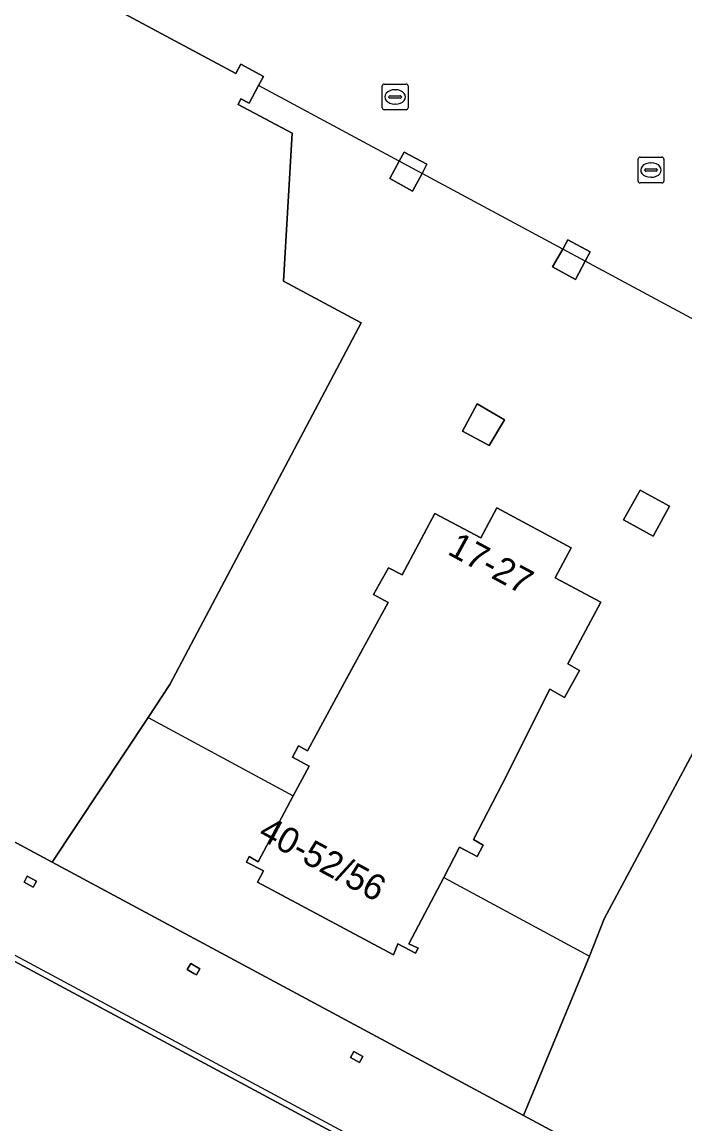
# Model space of a CAD drawing. Extents: x 159489 to 160304, y 383825 to 384531.
# Drawn here: x 159831.19 to 159856.94, y 384203.65 to 384246.47 of the extents above; entities that cross this region are included whole.
import ezdxf

# ---------------------------------------------------------------- set-up
doc = ezdxf.new("R2010")
doc.units = 0
for name, color, linetype in [('IMGEO_Kolk', 7, 'Continuous'), ('IMGEO_Lijnafwatering', 7, 'Continuous'), ('IMGEO_Pand', 7, 'Continuous'), ('IMGEO_Pand_nummerreeks', 7, 'Continuous'), ('IMGEO_Pand_overbouw', 7, 'Continuous'), ('IMGEO_Rioolput', 7, 'Continuous'), ('IMGEO_Voetpad_open', 7, 'Continuous')]:
    doc.layers.add(name, color=color, linetype=linetype)

msp = doc.modelspace()

# ---------------------------------------------------------------- linework, layer by layer
at = {"layer": 'IMGEO_Kolk'}
for p, q in [((159845.183, 384243.138), (159845.183, 384243.99)), ((159845.258, 384244.064), (159846.11, 384244.064)), ((159846.184, 384243.99), (159846.184, 384243.138)), ((159845.442, 384243.558), (159845.442, 384243.57)), ((159845.485, 384243.607), (159845.883, 384243.607)), ((159845.671, 384243.844), (159845.696, 384243.844)), ((159845.926, 384243.57), (159845.926, 384243.558)), ((159845.88, 384243.521), (159845.482, 384243.521)), ((159845.694, 384243.284), (159845.669, 384243.284)), ((159846.11, 384243.064), (159845.258, 384243.064))]:
    msp.add_line(p, q, dxfattribs=at)
for points in [[(159845.183, 384243.138), (159845.183, 384243.99)], [(159845.258, 384244.064), (159846.11, 384244.064)], [(159846.184, 384243.99), (159846.184, 384243.138)], [(159846.11, 384243.064), (159845.258, 384243.064)]]:
    msp.add_lwpolyline(points, dxfattribs=at)
for centre, radius, start, end in [((159845.26, 384243.988), 0.0765, 91.552, 178.448), ((159845.26, 384243.988), 0.0765, 91.552, 178.448), ((159846.108, 384243.988), 0.0765, 1.552, 88.448), ((159846.108, 384243.988), 0.0765, 1.552, 88.448), ((159845.482, 384243.567), 0.0403, 85.8775, 175.7526), ((159845.887, 384243.569), 0.0386, 1.7309, 96.639), ((159845.26, 384243.14), 0.0765, 181.552, 268.448), ((159845.26, 384243.14), 0.0765, 181.552, 268.448), ((159845.479, 384243.557), 0.0366, 178.938, 274.7102), ((159845.883, 384243.564), 0.043, 264.8664, 352.4533), ((159846.108, 384243.14), 0.0765, 271.552, 358.448), ((159846.108, 384243.14), 0.0765, 271.552, 358.448)]:
    msp.add_arc(centre, radius, start, end, dxfattribs=at)
for centre, major_axis, ratio, start_param, end_param in [((159845.67, 384243.564), (-0.387, 0.002), 0.722429, 4.712389, 7.853982), ((159845.695, 384243.564), (-0.39, 0.002), 0.717154, 1.570796, 4.712389)]:
    msp.add_ellipse(centre, major_axis=major_axis, ratio=ratio, start_param=start_param, end_param=end_param, dxfattribs=at)
at = {"layer": 'IMGEO_Lijnafwatering'}
for points in [[(159839.597, 384205.535), (159822.818, 384214.548)], [(159856.376, 384196.522), (159839.597, 384205.535)]]:
    msp.add_lwpolyline(points, dxfattribs=at)
at = {"layer": 'IMGEO_Pand'}
for points in [[(159806.759, 384227.581), (159832.355, 384213.828), (159836.092, 384219.448), (159836.928, 384220.726), (159844.358, 384234.78), (159841.346, 384236.404), (159841.688, 384242.153), (159839.589, 384243.272), (159839.694, 384243.496), (159840.01, 384243.32), (159840.376, 384244.002), (159840.57, 384244.359), (159839.69, 384244.84), (159839.497, 384244.475), (159834.054, 384247.399), (159834.25, 384247.76), (159833.369, 384248.239), (159833.176, 384247.87), (159827.698, 384250.814)], [(159861.301, 384225.632), (159853.801, 384211.617), (159853.229, 384210.167), (159850.676, 384203.98), (159876.265, 384190.214)]]:
    msp.add_lwpolyline(points, dxfattribs=at)
for points in [[(159846.92, 384240.95), (159846.04, 384241.419), (159845.846, 384241.062), (159845.477, 384240.399), (159846.363, 384239.905), (159846.729, 384240.587)], [(159853.26, 384237.539), (159852.39, 384238.01), (159852.199, 384237.648), (159851.793, 384236.955), (159852.69, 384236.473), (159853.07, 384237.18)], [(159849.929, 384231.009), (159848.871, 384231.633), (159848.299, 384230.579), (159849.342, 384230.013)], [(159854.562, 384227.129), (159855.707, 384226.495), (159856.347, 384227.652), (159855.202, 384228.286)], [(159852.846, 384221.265), (159852.392, 384221.529), (159853.673, 384223.928), (159851.9, 384224.877), (159852.52, 384226.034), (159849.631, 384227.59), (159849.008, 384226.426), (159847.232, 384227.377), (159845.952, 384224.987), (159845.425, 384225.265), (159844.841, 384224.225), (159845.41, 384223.915), (159843.988, 384221.304), (159842.274, 384218.155), (159841.928, 384218.344), (159841.698, 384217.902), (159842.342, 384217.559), (159841.725, 384216.397), (159840.363, 384213.832), (159840.01, 384214.04), (159839.913, 384213.826), (159840.567, 384213.482), (159840.331, 384213.041), (159845.618, 384210.218), (159845.788, 384210.654), (159846.476, 384210.283), (159846.574, 384210.481), (159846.211, 384210.648), (159847.571, 384213.231), (159848.188, 384214.403), (159848.871, 384214.044), (159849.102, 384214.486), (159848.722, 384214.704), (159849.86, 384216.884), (159851.696, 384220.543), (159852.263, 384220.225)], [(159831.752, 384213.085), (159831.394, 384213.279), (159831.266, 384213.043), (159831.624, 384212.849)], [(159838.102, 384209.679), (159837.751, 384209.884), (159837.61, 384209.644), (159837.867, 384209.494), (159837.964, 384209.442)], [(159844.433, 384206.265), (159844.085, 384206.457), (159843.956, 384206.224), (159844.305, 384206.032)]]:
    msp.add_lwpolyline(points, close=True, dxfattribs=at)
at = {"layer": 'IMGEO_Pand_overbouw'}
msp.add_lwpolyline([(159858.56, 384234.23), (159853.07, 384237.18), (159852.199, 384237.648), (159846.729, 384240.587), (159845.846, 384241.062), (159840.376, 384244.002), (159840.01, 384243.32), (159839.694, 384243.496), (159839.589, 384243.272), (159841.688, 384242.153), (159841.346, 384236.404), (159844.358, 384234.78), (159836.928, 384220.726), (159836.092, 384219.448), (159841.725, 384216.397), (159842.342, 384217.559), (159841.698, 384217.902), (159841.928, 384218.344), (159842.274, 384218.155), (159845.41, 384223.915), (159844.841, 384224.225), (159845.425, 384225.265), (159845.952, 384224.987), (159847.232, 384227.377), (159849.008, 384226.426), (159849.631, 384227.59), (159852.52, 384226.034), (159851.9, 384224.877), (159853.673, 384223.928), (159852.392, 384221.529), (159852.846, 384221.265), (159852.263, 384220.225), (159851.696, 384220.543), (159849.86, 384216.884), (159848.722, 384214.704), (159849.102, 384214.486), (159848.871, 384214.044), (159848.188, 384214.403), (159847.571, 384213.231), (159853.229, 384210.167), (159853.801, 384211.617), (159861.301, 384225.632)], dxfattribs=at)
at = {"layer": 'IMGEO_Rioolput'}
for p, q in [((159855.123, 384240.296), (159855.123, 384241.148)), ((159855.198, 384241.222), (159856.05, 384241.222)), ((159855.611, 384241.002), (159855.636, 384241.002)), ((159856.124, 384241.148), (159856.124, 384240.296)), ((159855.382, 384240.716), (159855.382, 384240.728)), ((159855.82, 384240.679), (159855.422, 384240.679)), ((159855.425, 384240.765), (159855.823, 384240.765)), ((159855.866, 384240.728), (159855.866, 384240.716)), ((159856.05, 384240.222), (159855.198, 384240.222)), ((159855.634, 384240.442), (159855.609, 384240.442))]:
    msp.add_line(p, q, dxfattribs=at)
for points in [[(159855.123, 384240.296), (159855.123, 384241.148)], [(159855.198, 384241.222), (159856.05, 384241.222)], [(159856.124, 384241.148), (159856.124, 384240.296)], [(159856.05, 384240.222), (159855.198, 384240.222)]]:
    msp.add_lwpolyline(points, dxfattribs=at)
for centre, radius, start, end in [((159855.2, 384241.146), 0.0765, 91.552, 178.448), ((159855.2, 384241.146), 0.0765, 91.552, 178.448), ((159856.048, 384241.146), 0.0765, 1.552, 88.448), ((159856.048, 384241.146), 0.0765, 1.552, 88.448), ((159855.422, 384240.725), 0.0403, 85.8775, 175.7526), ((159855.419, 384240.715), 0.0366, 178.938, 274.7102), ((159855.823, 384240.722), 0.043, 264.8664, 352.4533), ((159855.827, 384240.727), 0.0386, 1.7309, 96.639), ((159855.2, 384240.298), 0.0765, 181.552, 268.448), ((159855.2, 384240.298), 0.0765, 181.552, 268.448), ((159856.048, 384240.298), 0.0765, 271.552, 358.448), ((159856.048, 384240.298), 0.0765, 271.552, 358.448)]:
    msp.add_arc(centre, radius, start, end, dxfattribs=at)
for centre, major_axis, ratio, start_param, end_param in [((159855.61, 384240.722), (-0.387, 0.002), 0.722429, 4.712389, 7.853982), ((159855.635, 384240.722), (-0.39, 0.002), 0.717154, 1.570796, 4.712389)]:
    msp.add_ellipse(centre, major_axis=major_axis, ratio=ratio, start_param=start_param, end_param=end_param, dxfattribs=at)
at = {"layer": 'IMGEO_Voetpad_open'}
for points in [[(159834.054, 384247.399), (159839.497, 384244.475), (159839.69, 384244.84), (159840.57, 384244.359), (159840.376, 384244.002), (159840.01, 384243.32), (159839.694, 384243.496), (159839.589, 384243.272), (159841.688, 384242.153), (159841.346, 384236.404), (159844.358, 384234.78), (159836.928, 384220.726), (159836.092, 384219.448), (159832.355, 384213.828), (159850.676, 384203.98), (159853.229, 384210.167), (159853.801, 384211.617), (159861.301, 384225.632)], [(159786.709, 384224.175), (159811.286, 384210.982), (159830.635, 384200.595), (159841.233, 384194.906), (159846.022, 384192.335), (159850.876, 384189.729), (159870.224, 384179.343), (159880.668, 384173.736), (159888.635, 384169.463), (159893.253, 384178.177), (159891.472, 384180.7), (159875.43, 384189.271), (159875.566, 384189.534), (159875.806, 384189.41), (159876.265, 384190.214), (159850.676, 384203.98), (159832.355, 384213.828), (159806.759, 384227.581)]]:
    msp.add_lwpolyline(points, dxfattribs=at)
for points in [[(159846.729, 384240.587), (159846.363, 384239.905), (159845.477, 384240.399), (159845.846, 384241.062), (159846.04, 384241.419), (159846.92, 384240.95)], [(159851.793, 384236.955), (159852.199, 384237.648), (159852.39, 384238.01), (159853.26, 384237.539), (159853.07, 384237.18), (159852.69, 384236.473)], [(159890.081, 384178.186), (159789.088, 384232.417), (159786.238, 384227.228), (159886.537, 384173.398), (159887.304, 384172.975)], [(159890.081, 384178.186), (159887.304, 384172.975), (159886.537, 384173.398), (159786.238, 384227.228), (159789.088, 384232.417)], [(159849.929, 384231.009), (159849.342, 384230.013), (159848.299, 384230.579), (159848.871, 384231.633)], [(159855.202, 384228.286), (159856.347, 384227.652), (159855.707, 384226.495), (159854.562, 384227.129)], [(159852.52, 384226.034), (159851.9, 384224.877), (159853.673, 384223.928), (159852.392, 384221.529), (159852.846, 384221.265), (159852.263, 384220.225), (159851.696, 384220.543), (159849.86, 384216.884), (159848.722, 384214.704), (159849.102, 384214.486), (159848.871, 384214.044), (159848.188, 384214.403), (159847.571, 384213.231), (159846.211, 384210.648), (159846.574, 384210.481), (159846.476, 384210.283), (159845.788, 384210.654), (159845.618, 384210.218), (159840.331, 384213.041), (159840.567, 384213.482), (159839.913, 384213.826), (159840.01, 384214.04), (159840.363, 384213.832), (159841.725, 384216.397), (159842.342, 384217.559), (159841.698, 384217.902), (159841.928, 384218.344), (159842.274, 384218.155), (159843.988, 384221.304), (159845.41, 384223.915), (159844.841, 384224.225), (159845.425, 384225.265), (159845.952, 384224.987), (159847.232, 384227.377), (159849.008, 384226.426), (159849.631, 384227.59)], [(159831.266, 384213.043), (159831.394, 384213.279), (159831.752, 384213.085), (159831.624, 384212.849)], [(159837.867, 384209.494), (159837.61, 384209.644), (159837.751, 384209.884), (159838.102, 384209.679), (159837.964, 384209.442)], [(159844.085, 384206.457), (159844.433, 384206.265), (159844.305, 384206.032), (159843.956, 384206.224)]]:
    msp.add_lwpolyline(points, close=True, dxfattribs=at)

# ---------------------------------------------------------------- texts
at = {"layer": 'IMGEO_Pand_nummerreeks'}
for s, rotation, p in [('17-27', 331.4953, (159847.674, 384225.813)), ('40-52/56', 331.7016, (159840.315, 384214.765))]:
    msp.add_text(s, height=1, rotation=rotation, dxfattribs=at).set_placement(p)

doc.saveas('drawing.dxf')
